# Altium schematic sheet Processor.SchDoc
size A4; Author: Michał Wojna; CompanyName: AGH; Revision: 1
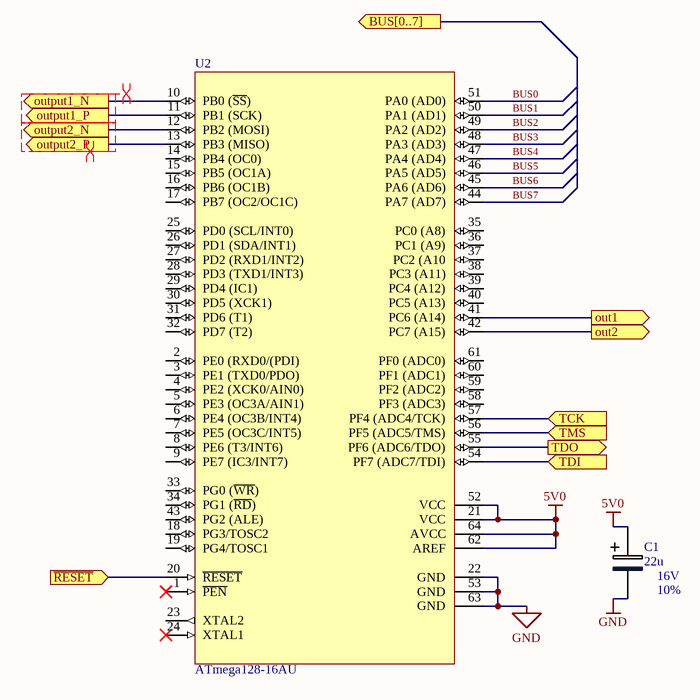
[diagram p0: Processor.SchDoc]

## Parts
C1  22u  Rated Voltage: 16V  Tolerance: 10%  [VJ_Tantalum_A]
U2  ATmega128-16AU  [64A_N]

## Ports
BUS[0..7] (out), out1 (out), out2 (out), output1_N (out), output1_P (out), output2_N (out), output2_P (out), TCK (in), TDI (in), TDO (out), TMS (in), ~{RESET} (in)

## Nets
5V0: C1.1 U2.21(VCC) U2.52(VCC) U2.62(AREF) U2.64(AVCC)
GND: C1.2 U2.22(GND) U2.53(GND) U2.63(GND)
BUS0: U2.51(PA0_(AD0))
BUS1: U2.50(PA1_(AD1))
BUS2: U2.49(PA2_(AD2))
BUS3: U2.48(PA3_(AD3))
BUS4: U2.47(PA4_(AD4))
BUS5: U2.46(PA5_(AD5))
BUS6: U2.45(PA6_(AD6))
BUS7: U2.44(PA7_(AD7))
out1: U2.41(PC6_(A14)) ; port out1
out2: U2.42(PC7_(A15)) ; port out2
output1_N: U2.10(PB0_(~{SS})) ; port output1_N
output1_P: U2.11(PB1_(SCK)) ; port output1_P
output2_N: U2.12(PB2_(MOSI)) ; port output2_N
output2_P: U2.13(PB3_(MISO)) ; port output2_P
~{RESET}: U2.20(~{RESET}) ; port ~{RESET}
TCK: U2.57(PF4_(ADC4/TCK)) ; port TCK
TDI: U2.54(PF7_(ADC7/TDI)) ; port TDI
TDO: U2.55(PF6_(ADC6/TDO)) ; port TDO
TMS: U2.56(PF5_(ADC5/TMS)) ; port TMS

Not connected (* = marked no-connect by the designer): U2 1(~{PEN})* 2(PE0_(RXD0/(PDI)) 3(PE1_(TXD0/PDO)) 4(PE2_(XCK0/AIN0)) 5(PE3_(OC3A/AIN1)) 6(PE4_(OC3B/INT4)) 7(PE5_(OC3C/INT5)) 8(PE6_(T3/INT6)) 9(PE7_(IC3/INT7)) 14(PB4_(OC0)) 15(PB5_(OC1A)) 16(PB6_(OC1B)) 17(PB7_(OC2/OC1C)) 18(PG3/TOSC2) 19(PG4/TOSC1) 23(XTAL2) 24(XTAL1)* 25(PD0_(SCL/INT0)) 26(PD1_(SDA/INT1)) 27(PD2_(RXD1/INT2)) 28(PD3_(TXD1/INT3)) 29(PD4_(IC1)) 30(PD5_(XCK1)) 31(PD6_(T1)) 32(PD7_(T2)) 33(PG0_(~{WR})) 34(PG1_(~{RD})) 35(PC0_(A8)) 36(PC1_(A9)) 37(PC2_(A10) 38(PC3_(A11)) 39(PC4_(A12)) 40(PC5_(A13)) 43(PG2_(ALE)) 58(PF3_(ADC3)) 59(PF2_(ADC2)) 60(PF1_(ADC1)) 61(PF0_(ADC0))

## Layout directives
differential pair: (no net found under the mark)

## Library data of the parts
C1 = Capacitor_polarized: Manufacturer: VJ; Part Number: 293D223X9016D2TE3; Vendor: Farnell
U2 = ATmega128-16AU: 8-bit AVR Microcontroller, 4.5-5.5V, 128KB Flash, 4KB EEPROM, 4KB SRAM, 64-pin TQFP, Industrial Grade (-40°C to 85°C)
